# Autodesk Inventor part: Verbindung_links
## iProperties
Created: 2007-03
Part Number: Verbindung_links
Cost Center: 40,78 kg
Material: S235JRG2
Document SubType Name: Blech
Designer: Chako
Authority: 5195041,4 mm^3
SaveDate: 2007-03-16
SaveTime: 17:17
FileName: Verbindung_links
TotalMass: 40,78 kg
TotalVolume: 5195041,4 mm^3
SM_Thickness: 6 mm
SM_Style: Standard
SM_Extents: 308,47 mm x 2800,00 mm
SM_Square: 863712 mm²
SM_Extents_Width: 308,47 mm
SM_Extents_Length: 2800,00 mm
Author: Chako
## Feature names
1. Extrusion2
2. Extrusion3
3. Wandstärke1
4. Rundung1 [Fillet]
